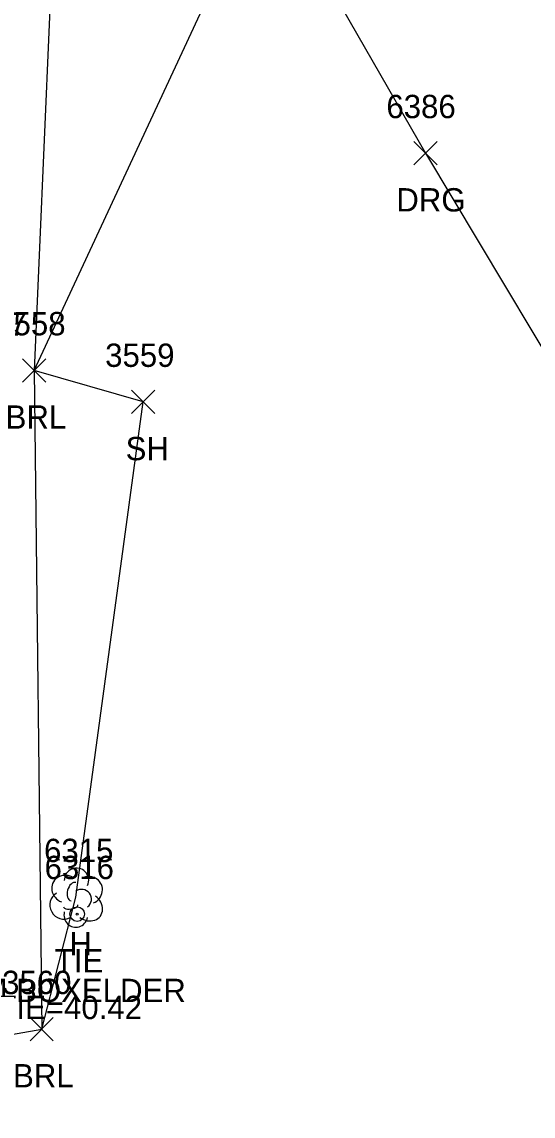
# Model space of a CAD drawing. Extents: x 1462668 to 1465147, y 550359 to 557351.
# Drawn here: x 1464985.2 to 1465029, y 551065.4 to 551159.2 of the extents above; entities that cross this region are included whole.
import ezdxf

# ---------------------------------------------------------------- set-up
doc = ezdxf.new("R2010")
doc.units = 0
for name, color, linetype in [('C_A', 7, 'Continuous'), ('C_C', 7, 'Continuous'), ('C_I', 7, 'Continuous'), ('CBP', 7, 'Continuous'), ('L_A', 7, 'Continuous'), ('L_C', 7, 'Continuous'), ('L_I', 7, 'Continuous'), ('L_TIC', 7, 'Continuous'), ('LABL', 7, 'Continuous'), ('Level 6', 7, 'Continuous'), ('LTD', 7, 'Continuous'), ('R_A', 7, 'Continuous'), ('R_I', 7, 'Continuous'), ('R_TIC', 7, 'Continuous'), ('RDG', 7, 'Continuous')]:
    doc.layers.add(name, color=color, linetype=linetype)

msp = doc.modelspace()

# ---------------------------------------------------------------- linework, layer by layer
at = {"layer": 'CBP'}
for radius in [0.625, 0.0833]:
    msp.add_circle((1464989.928, 551082.748), radius, dxfattribs=at)
at = {"layer": 'L_TIC'}
for points in [[(1464985.243, 551128.355), (1464987.243, 551130.355)], [(1464987.243, 551128.355), (1464985.243, 551130.355)], [(1464994.597, 551125.651), (1464996.597, 551127.651)], [(1464996.597, 551125.651), (1464994.597, 551127.651)], [(1464985.883, 551071.892), (1464987.883, 551073.892)], [(1464987.883, 551071.892), (1464985.883, 551073.892)]]:
    msp.add_lwpolyline(points, dxfattribs=at)
at = {"layer": 'LABL'}
msp.add_lwpolyline([(1464988.8, 551188.67), (1464986.243, 551129.355), (1464986.883, 551072.892)], dxfattribs=at)
at = {"layer": 'Level 6'}
msp.add_lwpolyline([(1464977.741, 551071.271), (1464986.883, 551072.892), (1464989.827, 551084.205), (1464995.597, 551126.651), (1464986.243, 551129.355), (1465006.045, 551171.907)], dxfattribs=at)
at = {"layer": 'LTD'}
msp.add_line((1464989.827, 551084.205), (1464989.827, 551084.205), dxfattribs=at)
msp.add_line((1464989.827, 551084.205), (1464989.827, 551084.205), dxfattribs=at)
msp.add_arc((1464989.873, 551085.639), 1.047, 335.52715, 180.95627, dxfattribs=at)
for centre, major_axis, ratio, start_param, end_param in [((1464989.035, 551084.871), (1.21, -0.512), 0.895232, 1.570796, 4.712389), ((1464989.618, 551084.663), (-0.208, -0.792), 0.645439, 3.141593, 6.283185), ((1464990.868, 551084.788), (-1.141, -0.483), 0.949671, 1.570796, 4.712389), ((1464988.743, 551083.496), (0.584, -1.042), 0.959034, 3.141593, 6.283185), ((1464990.327, 551084.038), (-0.5, 0.667), 0.989748, 3.141593, 6.283185), ((1464989.368, 551083.455), (-0.625, -0.083), 0.423636, 0, 3.141593), ((1464990.827, 551083.372), (-1.09, 0.792), 0.841452, 1.570796, 4.712389), ((1464989.827, 551082.705), (0.265, 1.061), 0.942809, 1.570796, 4.712389)]:
    msp.add_ellipse(centre, major_axis=major_axis, ratio=ratio, start_param=start_param, end_param=end_param, dxfattribs=at)
at = {"layer": 'R_TIC'}
for points in [[(1465018.819, 551146.97), (1465020.819, 551148.97)], [(1465020.819, 551146.97), (1465018.819, 551148.97)]]:
    msp.add_lwpolyline(points, dxfattribs=at)
at = {"layer": 'RDG'}
msp.add_lwpolyline([(1464982.382, 551474.171), (1464986.329, 551432.77), (1464987.126, 551369.978), (1464986.122, 551312.327), (1464985.912, 551263.053), (1464987.337, 551228.97), (1464997.781, 551186.268), (1465019.819, 551147.97), (1465035.784, 551121.294), (1465053.953, 551092.087), (1465070.138, 551076.148), (1465084.431, 551065.432)], dxfattribs=at)

# ---------------------------------------------------------------- texts
at = {"layer": 'C_A'}
msp.add_text('TIE', height=2, dxfattribs=at).set_placement((1464988.007, 551077.748))
at = {"layer": 'C_C'}
msp.add_text('TIE=40.42', height=2, dxfattribs=at).set_placement((1464983.078, 551073.748))
at = {"layer": 'C_I'}
msp.add_text('6316', height=2, dxfattribs=at).set_placement((1464987.133, 551085.748))
at = {"layer": 'L_A'}
for s, p in [('BRL', (1464983.787, 551124.355)), ('SH', (1464994.086, 551121.651)), ('H', (1464989.26, 551079.205)), ('BRL', (1464984.426, 551067.892))]:
    msp.add_text(s, height=2, dxfattribs=at).set_placement(p)
at = {"layer": 'L_C'}
msp.add_text('2M.BOXELDER', height=2, dxfattribs=at).set_placement((1464980.228, 551075.205))
at = {"layer": 'L_I'}
for s, p in [('3557', (1464979.658, 551132.323)), ('3558', (1464982.983, 551132.355)), ('3559', (1464992.33, 551129.651)), ('6315', (1464987.086, 551087.205)), ('3560', (1464983.489, 551075.892))]:
    msp.add_text(s, height=2, dxfattribs=at).set_placement(p)
at = {"layer": 'R_A'}
msp.add_text('DRG', height=2, dxfattribs=at).set_placement((1465017.307, 551142.97))
at = {"layer": 'R_I'}
msp.add_text('6386', height=2, dxfattribs=at).set_placement((1465016.457, 551150.97))

doc.saveas('drawing.dxf')
